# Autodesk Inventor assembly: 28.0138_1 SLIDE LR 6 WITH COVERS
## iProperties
Created: 2007-06
Part Number: 28.0138_1 SLIDE LR 6 WITH COVERS
Document SubType Name: Assembly
Designer: Andy Moles
Mass: 498.397 g
Surface Area: 693.428 cm^2
Volume: 150.621 cm^3
Density: 3.30895 g/cm^3
Author: Andy Moles
